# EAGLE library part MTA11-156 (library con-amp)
AMP connector
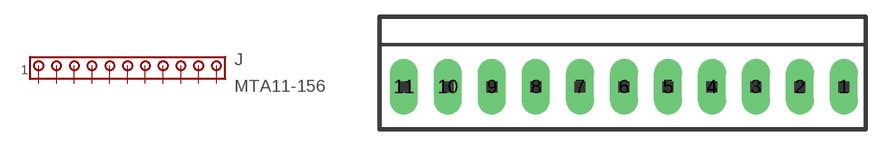
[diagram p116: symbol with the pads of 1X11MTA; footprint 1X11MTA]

Designator prefix J

## MTA11-156 (OC_FARNELL: unknown; OC_NEWARK: unknown)  [1X11MTA]
1  1  pas
2  2  pas
3  3  pas
4  4  pas
5  5  pas
6  6  pas
7  7  pas
8  8  pas
9  9  pas
10  10  pas
11  11  pas

## Footprint 1X11MTA (pad centres in mm)
AMP MTA connector
drill 1.676 long: 1 19.812,0; 2 15.85,0; 3 11.887,0; 4 7.925,0; 5 3.962,0; 6 0,0; 7 -3.962,0; 8 -7.925,0; 9 -11.887,0; 10 -15.85,0; 11 -19.812,0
